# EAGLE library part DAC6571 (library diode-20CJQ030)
Ti's DAC6571 10-BIT DIGITAL-TO-ANALOG CONVERTER Features: Micropower Operation: 125 µA @ 3 V Fast Update Rate: 188 kSPS Power-On Reset to Zero +2.7 V to +5.5 V Power Supply Specified Monotonic by Design I2C? Interface up to 3.4 Mbps On-Chip Output Buffer Amplifier, Rail-to-Rail Operation Double-Buffered Input Register Address Support for up to Two DAC6571s Small 6 Lead SOT 23 Package Operation From -40°C to 105°C Application: Process Control Data Acquistion Systems Closed-Loop Servo Control PC Peripherals Portable Instrumentation Description: The DAC6571 is a low-power, single channel, 10-Bit buffered voltage output DAC. Its on-chip precision output amplifier allows rail-to-rail output swing to be achieved. The DAC6571 utilizes an I2C compatible two wire serial interface that operates at clock rates up to 3.4 Mbps with address support of up to two DAC6571s on the same data bus. The output voltage range of the DAC is 0 V to VDD. The DAC6571 incorporates a power-on-reset circuit that ensures that the DAC output powers up at zero volts and remains there until a valid write to the device takes place. The DAC6571 contains a power-down feature, accessed via the internal control register, that reduces the current consumption of the device to 50 nA at 5 V. The low power consumption of this part in normal operation makes it ideally suited for portable battery operated equipment. The power consumption is less than 0.7 mW at VDD = 5 V reducing to 1 µW in power-down mode.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
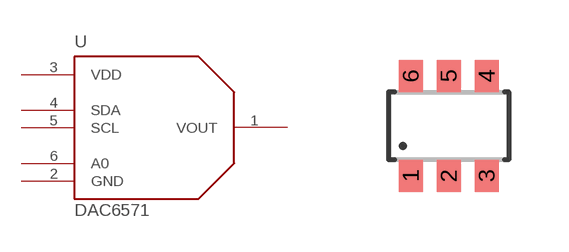
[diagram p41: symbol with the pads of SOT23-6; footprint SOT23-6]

Designator prefix U

## DAC6571  [SOT23-6]
1  VOUT  pas
2  GND  pwr
3  VDD  pwr
4  SDA
5  SCL
6  A0  in

## Footprint SOT23-6 (pad centres in mm)
Small Outline Transistor 6 lead
smd 0.6 x 0.8: 1 -0.95,-1.25; 2 0,-1.25; 3 0.95,-1.25; 4 0.95,1.25; 5 0,1.25; 6 -0.95,1.25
